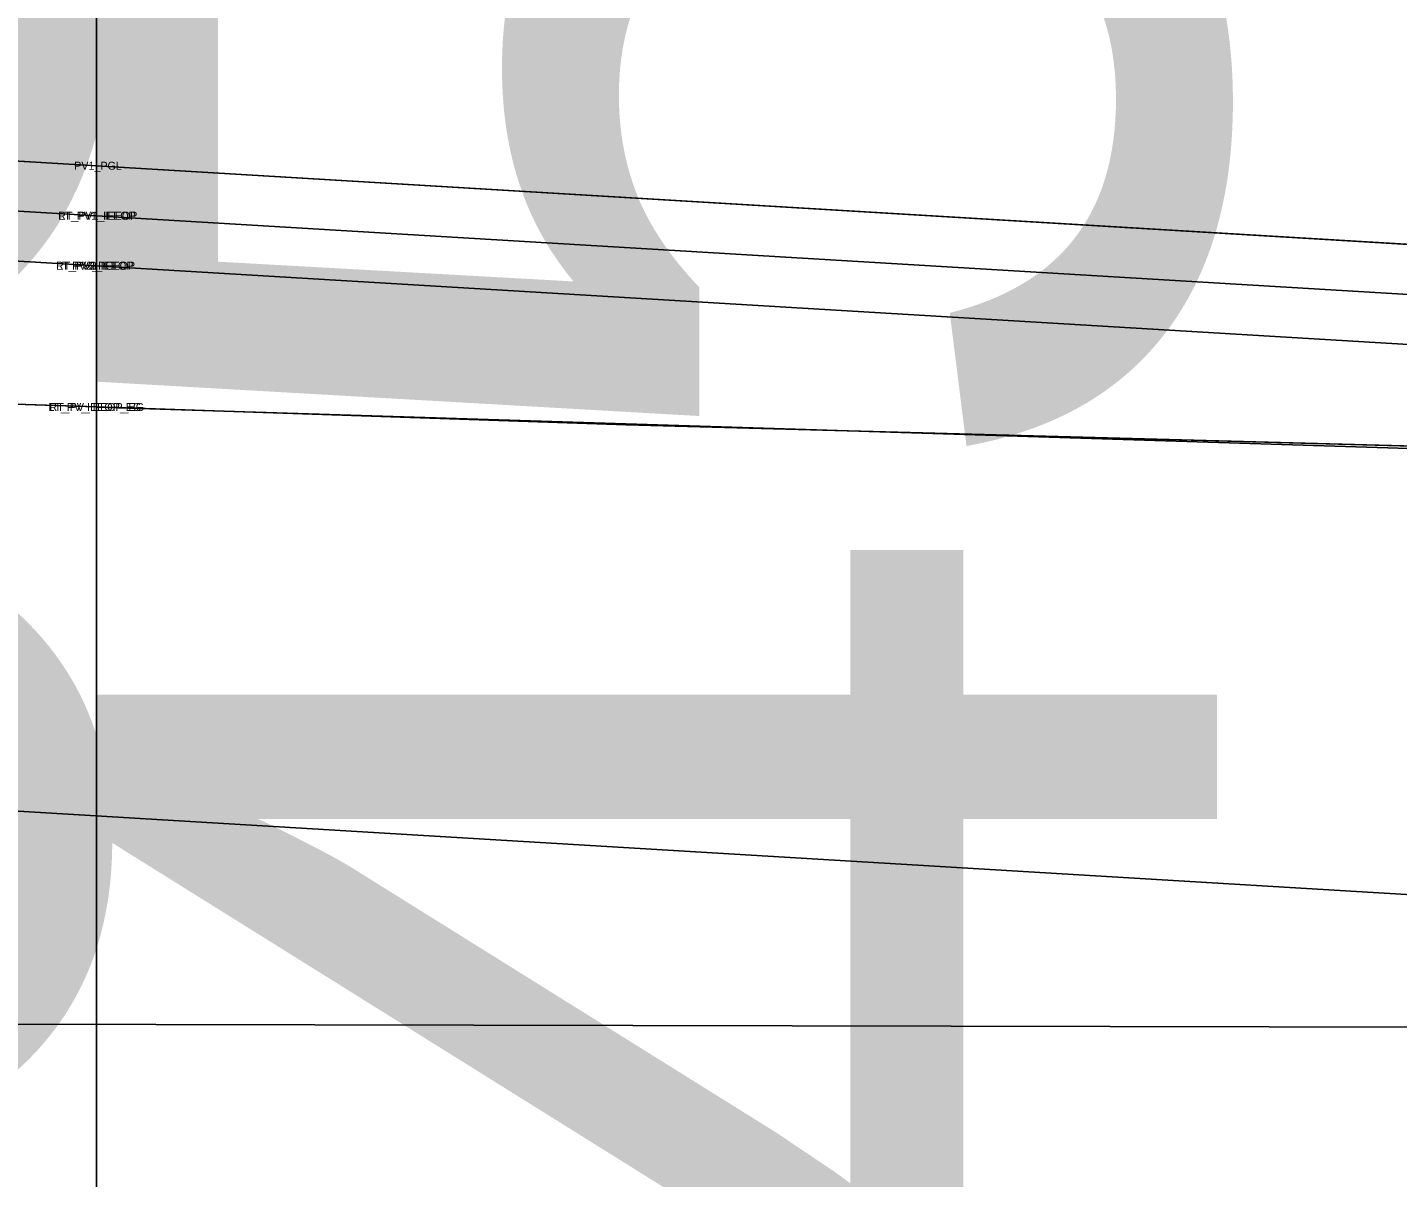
# Model space of a CAD drawing. Extents: x -516 to 303, y -10 to 5017.
# Drawn here: x 149.828 to 153.251, y 3502.271 to 3505.146 of the extents above; entities that cross this region are included whole.
import ezdxf

# ---------------------------------------------------------------- set-up
doc = ezdxf.new("R2010")
doc.units = 0
for name, color, linetype in [('Exist CMT Pavement', 7, 'Continuous'), ('Exist Cross Section Cell', 7, 'Continuous'), ('Exist XS Ground Line', 7, 'Continuous'), ('Prop CMT Pvmt Course 1', 7, 'Continuous'), ('Prop CMT Pvmt Course 1 Wedge', 7, 'Continuous'), ('Prop CMT Pvmt Course 2 Wedge', 7, 'Continuous'), ('Prop CMT Pvmt Course 3 Wedge', 7, 'Continuous'), ('Prop CMT Pvmt Surface', 7, 'Continuous'), ('Prop CMT Pvmt Wedge Surface 1', 7, 'Continuous'), ('Prop CMT Pvmt Wedge Surface 2', 7, 'Continuous'), ('Prop CMT Pvmt Wedge Surface 3', 7, 'Continuous'), ('Prop Road Sect_ Material - Contact (General - Major)', 7, 'Continuous'), ('Prop Road Sect_ Misc - Drafting Aid (solid line)', 7, 'Continuous'), ('Prop Road Sect_ Recs - UC Shallow (Outline)', 7, 'Continuous'), ('Prop Road Sect_ Recs - UC Shallow (Pattern)', 7, 'Continuous'), ('Scratch_Level_0', 7, 'Continuous')]:
    doc.layers.add(name, color=color, linetype=linetype)

msp = doc.modelspace()

# ---------------------------------------------------------------- linework, layer by layer
at = {"layer": 'Exist CMT Pavement'}
for points in [[(149.9985, 3504.197), (148.0015, 3504.2629)], [(150.0015, 3504.1969), (161.5277, 3503.8336)]]:
    msp.add_lwpolyline(points, dxfattribs=at)
at = {"layer": 'Exist Cross Section Cell'}
msp.add_line((150, 3500), (150, 3518.6918), dxfattribs=at)
at = {"layer": 'Exist XS Ground Line'}
msp.add_lwpolyline([(125.205, 3503.8945), (131.7518, 3504.2176), (136.6829, 3504.4743), (138.318, 3504.4836), (148.612, 3504.249), (149.068, 3504.2286), (150, 3504.197), (151.3235, 3504.1521), (153.2258, 3504.1006), (154.2229, 3504.0743), (155.6813, 3504.0239), (157.1104, 3503.9729), (158.1124, 3503.9391), (159.3093, 3503.9003), (160.0118, 3503.8781), (163.151, 3503.7853), (163.5861, 3503.7651), (164.5345, 3503.7181), (165.9518, 3503.6102), (166.3074, 3503.5849)], dxfattribs=at)
at = {"layer": 'Prop CMT Pvmt Course 1'}
for points in [[(150, 3504.8), (148, 3504.92)], [(148, 3504.795), (150, 3504.675)], [(150, 3504.55), (150, 3504.8)], [(150, 3504.8), (161.5292, 3504.1082)], [(150, 3504.55), (150, 3504.8)], [(150, 3504.675), (150, 3504.55), (150, 3504.55)], [(161.5292, 3503.9832), (150, 3504.675)], [(150, 3504.675), (150, 3504.55), (150, 3504.55)]]:
    msp.add_lwpolyline(points, dxfattribs=at)
at = {"layer": 'Prop CMT Pvmt Course 1 Wedge'}
for points in [[(150, 3504.675), (148, 3504.795)], [(150, 3504.675), (161.5292, 3503.9832)]]:
    msp.add_lwpolyline(points, dxfattribs=at)
at = {"layer": 'Prop CMT Pvmt Course 2 Wedge'}
for points in [[(150, 3504.55), (148, 3504.67)], [(150, 3504.55), (161.5292, 3503.8582)]]:
    msp.add_lwpolyline(points, dxfattribs=at)
at = {"layer": 'Prop CMT Pvmt Course 3 Wedge'}
for points in [[(150, 3504.55), (148, 3504.67)], [(150, 3504.55), (161.5292, 3503.8582)]]:
    msp.add_lwpolyline(points, dxfattribs=at)
at = {"layer": 'Prop CMT Pvmt Surface'}
for q in [(148, 3504.92), (161.5292, 3504.1082)]:
    msp.add_line((150, 3504.8), q, dxfattribs=at)
at = {"layer": 'Prop CMT Pvmt Wedge Surface 1'}
for points in [[(150, 3504.675), (148, 3504.795)], [(150, 3504.675), (161.5292, 3503.9832)]]:
    msp.add_lwpolyline(points, dxfattribs=at)
at = {"layer": 'Prop CMT Pvmt Wedge Surface 2'}
for points in [[(150, 3504.55), (148, 3504.67)], [(150, 3504.55), (161.5292, 3503.8582)]]:
    msp.add_lwpolyline(points, dxfattribs=at)
at = {"layer": 'Prop CMT Pvmt Wedge Surface 3'}
for points in [[(150, 3504.55), (148, 3504.67)], [(150, 3504.55), (161.5292, 3503.8582)]]:
    msp.add_lwpolyline(points, dxfattribs=at)
at = {"layer": 'Prop Road Sect_ Material - Contact (General - Major)'}
msp.add_line((176.8467, 3502.6017), (116.479, 3502.7189), dxfattribs=at)
at = {"layer": 'Prop Road Sect_ Misc - Drafting Aid (solid line)'}
msp.add_line((150, 3502.6538), (150, 3501.2538), dxfattribs=at)
at = {"layer": 'Prop Road Sect_ Recs - UC Shallow (Outline)'}
msp.add_lwpolyline([(165.1941, 3503.3234), (165.1941, 3503.6679), (164.5345, 3503.7181), (163.5861, 3503.7651), (163.151, 3503.7853), (159.3093, 3503.9003), (158.1124, 3503.9391), (157.1104, 3503.9729), (155.6813, 3504.0239), (154.2229, 3504.0743), (151.3235, 3504.1521), (150, 3504.197), (149.068, 3504.2286), (148.612, 3504.249), (148.0014, 3504.2629), (145.4104, 3504.322), (145.4104, 3503.4504), (148, 3503.295), (161.5292, 3502.4832), (164.1941, 3502.3234), (165.1941, 3502.3234), (165.1941, 3503.3234)], dxfattribs=at)
at = {"layer": 'Prop Road Sect_ Recs - UC Shallow (Pattern)'}
msp.add_lwpolyline([(165.1941, 3503.3234), (165.1941, 3503.6679), (164.5345, 3503.7181), (163.5861, 3503.7651), (163.151, 3503.7853), (159.3093, 3503.9003), (158.1124, 3503.9391), (157.1104, 3503.9729), (155.6813, 3504.0239), (154.2229, 3504.0743), (151.3235, 3504.1521), (150, 3504.197), (149.068, 3504.2286), (148.612, 3504.249), (148.0014, 3504.2629), (145.4104, 3504.322), (145.4104, 3503.4504), (148, 3503.295), (161.5292, 3502.4832), (164.1941, 3502.3234), (165.1941, 3502.3234), (165.1941, 3503.3234)], dxfattribs=at)

# ---------------------------------------------------------------- texts
at = {"layer": 'Exist Cross Section Cell'}
for s, p in [('E 2266450.6163', (152.8, 3490)), ('N 511503.2988', (150, 3490))]:
    msp.add_text(s, height=2.8, rotation=90, dxfattribs=at).set_placement(p)
at = {"layer": 'Scratch_Level_0'}
for s, p in [('PV1_PGL', (149.9447, 3504.79)), ('RT_PV1_IEEOP', (149.9047, 3504.665)), ('LT_PV1_IEEOP', (149.9052, 3504.665)), ('RT_PV2_IEEOP', (149.8991, 3504.54)), ('RT_PV3_IEEOP', (149.8991, 3504.54)), ('LT_PV2_IEEOP', (149.8995, 3504.54)), ('LT_PV3_IEEOP', (149.8995, 3504.54)), ('PV2_PGL', (149.9391, 3504.54)), ('LT_PV_IEEOP_EG', (149.8804, 3504.187)), ('RT_PV_IEEOP_EG', (149.8829, 3504.1869))]:
    msp.add_text(s, height=0.02, dxfattribs=at).set_placement(p)

doc.saveas('drawing.dxf')
